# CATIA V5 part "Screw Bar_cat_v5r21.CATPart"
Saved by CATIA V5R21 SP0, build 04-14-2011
Part number: Screw Bar
Bounding box of the stored display mesh (mm): x -3 to 3, y -52 to 52, z -2.853 to 2.853
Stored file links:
  D:\CATIA V5R21 E-RESOURCES\CATIA-V5R21\catia-v5r21-Tut\c13-catia-v5r21-tut\c13-catia-v5r21-tut02\Bench Vice\Screw Bar_cat_v5r21.CATPart
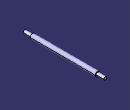
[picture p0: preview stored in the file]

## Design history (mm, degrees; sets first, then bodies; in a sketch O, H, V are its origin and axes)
Body1 (main body)
  Sketch1 on zx-plane, origin (0, 0, 0), H (-1, 0, 0), V (0, 0, 1)
    circle A1 centre (0, 0) radius 2
    radius A1 = 2
  Sketch2 on zx-plane, origin (0, 0, 0), H (-1, 0, 0), V (0, 0, 1)
    circle A1 centre (0, 0) radius 3
    radius A1 = 3
  Pad1: profile Sketch1, direction (0, 1, 0), length 52, mirrored extent
  Pad2: profile Sketch2, direction (0, 1, 0), length 42, mirrored extent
